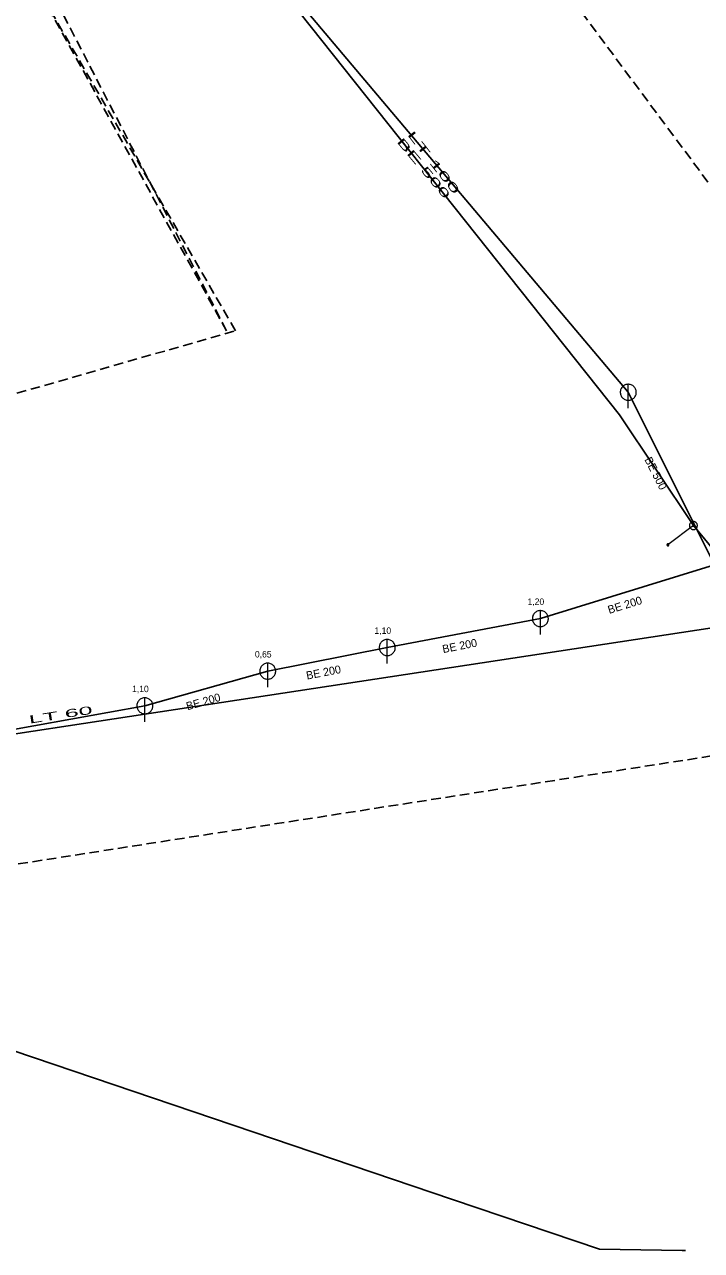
# Model space of a CAD drawing. Extents: x -689820 to -689363, y -975369 to -975062.
# Drawn here: x -689628.7 to -689544.2, y -975368.9 to -975215.7 of the extents above; entities that cross this region are included whole.
import ezdxf

# ---------------------------------------------------------------- set-up
doc = ezdxf.new("R2010")
doc.units = 0
doc.header["$LTSCALE"] = 0.4
doc.linetypes.add('MEDIUM_DASHED', pattern=[4.5, 3, -1.5])
doc.layers.add('1', color=7, linetype='Continuous')
for name, color, linetype, lineweight in [('14', 7, 'Continuous', 25), ('17', 7, 'Continuous', 25), ('22', 7, 'Continuous', 13), ('47', 7, 'Continuous', 13), ('63', 7, 'MEDIUM_DASHED', 25), ('9', 7, 'Continuous', 13)]:
    doc.layers.add(name, color=color, linetype=linetype, lineweight=lineweight)

msp = doc.modelspace()

# ---------------------------------------------------------------- linework, layer by layer
at = {"layer": '14'}
for p, q in [((-689553.342, -975261.657), (-689604.392, -975201.087)), ((-689598.372, -975296.513), (-689583.441, -975293.556)), ((-689613.713, -975300.842), (-689598.372, -975296.513)), ((-689648.44, -975307.089), (-689613.713, -975300.842))]:
    msp.add_line(p, q, dxfattribs=at)
at = {"layer": '14', "lineweight": 13}
msp.add_line((-689545.213, -975278.312), (-689548.389, -975280.719), dxfattribs=at)
at = {"layer": '14'}
msp.add_lwpolyline([(-689583.441, -975293.556), (-689564.324, -975289.938), (-689542.572, -975283.204), (-689553.342, -975261.657)], dxfattribs=at)
at = {"layer": '17'}
msp.add_line((-689536.239, -975289.23), (-689545.213, -975278.312), dxfattribs=at)
for points in [[(-689545.213, -975278.312), (-689554.449, -975264.469), (-689605.354, -975200.364), (-689609.803, -975191.467), (-689614.585, -975177.62)], [(-689536.351, -975289.602), (-689537.203, -975289.743), (-689537.12, -975290.232), (-689713.89, -975317.113)], [(-689546.18, -975368.915), (-689546.615, -975368.909), (-689556.942, -975368.745), (-689575.305, -975362.528), (-689637.592, -975341.438), (-689647.677, -975338.907), (-689651.947, -975337.591), (-689675.142, -975330.715), (-689713.978, -975319.23), (-689713.89, -975317.113)]]:
    msp.add_lwpolyline(points, dxfattribs=at)
at = {"layer": '22'}
for p, q in [((-689553.342, -975263.657), (-689553.341, -975260.657)), ((-689564.324, -975291.938), (-689564.323, -975288.938)), ((-689583.441, -975295.556), (-689583.44, -975292.556)), ((-689598.372, -975298.513), (-689598.371, -975295.513)), ((-689613.713, -975302.842), (-689613.712, -975299.842))]:
    msp.add_line(p, q, dxfattribs=at)
for points in [[(-689552.342, -975261.657), (-689552.347, -975261.548), (-689552.365, -975261.44), (-689552.395, -975261.334), (-689552.435, -975261.233), (-689552.487, -975261.136), (-689552.549, -975261.046), (-689552.621, -975260.963), (-689552.701, -975260.889), (-689552.789, -975260.823), (-689552.883, -975260.768), (-689552.983, -975260.723), (-689553.088, -975260.69), (-689553.195, -975260.668), (-689553.304, -975260.658), (-689553.414, -975260.66), (-689553.522, -975260.674), (-689553.629, -975260.699), (-689553.732, -975260.736), (-689553.83, -975260.785), (-689553.922, -975260.843), (-689554.008, -975260.912), (-689554.085, -975260.989), (-689554.154, -975261.075), (-689554.213, -975261.167), (-689554.261, -975261.265), (-689554.298, -975261.368), (-689554.324, -975261.475), (-689554.338, -975261.583), (-689554.341, -975261.693), (-689554.331, -975261.802), (-689554.31, -975261.909), (-689554.276, -975262.013), (-689554.232, -975262.113), (-689554.177, -975262.208), (-689554.111, -975262.296), (-689554.037, -975262.376), (-689553.954, -975262.448), (-689553.864, -975262.51), (-689553.768, -975262.562), (-689553.666, -975262.603), (-689553.561, -975262.633), (-689553.453, -975262.651), (-689553.343, -975262.657), (-689553.234, -975262.651), (-689553.126, -975262.633), (-689553.021, -975262.604), (-689552.919, -975262.563), (-689552.822, -975262.511), (-689552.732, -975262.449), (-689552.649, -975262.378), (-689552.574, -975262.298), (-689552.509, -975262.21), (-689552.453, -975262.116), (-689552.409, -975262.016), (-689552.375, -975261.912), (-689552.353, -975261.804), (-689552.343, -975261.695)], [(-689563.324, -975289.938), (-689563.329, -975289.829), (-689563.347, -975289.721), (-689563.377, -975289.615), (-689563.417, -975289.514), (-689563.469, -975289.417), (-689563.531, -975289.327), (-689563.603, -975289.244), (-689563.683, -975289.17), (-689563.771, -975289.104), (-689563.865, -975289.049), (-689563.965, -975289.004), (-689564.07, -975288.971), (-689564.177, -975288.949), (-689564.286, -975288.939), (-689564.396, -975288.941), (-689564.504, -975288.955), (-689564.611, -975288.98), (-689564.714, -975289.017), (-689564.812, -975289.066), (-689564.904, -975289.124), (-689564.99, -975289.193), (-689565.067, -975289.27), (-689565.136, -975289.356), (-689565.195, -975289.448), (-689565.243, -975289.546), (-689565.28, -975289.649), (-689565.306, -975289.756), (-689565.32, -975289.864), (-689565.323, -975289.974), (-689565.313, -975290.083), (-689565.292, -975290.19), (-689565.258, -975290.294), (-689565.214, -975290.394), (-689565.159, -975290.489), (-689565.093, -975290.577), (-689565.019, -975290.657), (-689564.936, -975290.729), (-689564.846, -975290.791), (-689564.75, -975290.843), (-689564.648, -975290.884), (-689564.543, -975290.914), (-689564.435, -975290.932), (-689564.325, -975290.938), (-689564.216, -975290.932), (-689564.108, -975290.914), (-689564.003, -975290.885), (-689563.901, -975290.844), (-689563.804, -975290.792), (-689563.714, -975290.73), (-689563.631, -975290.659), (-689563.556, -975290.579), (-689563.491, -975290.491), (-689563.435, -975290.397), (-689563.391, -975290.297), (-689563.357, -975290.193), (-689563.335, -975290.085), (-689563.325, -975289.976)], [(-689582.441, -975293.556), (-689582.446, -975293.447), (-689582.464, -975293.339), (-689582.494, -975293.233), (-689582.534, -975293.132), (-689582.586, -975293.035), (-689582.648, -975292.945), (-689582.72, -975292.862), (-689582.8, -975292.788), (-689582.888, -975292.722), (-689582.982, -975292.667), (-689583.082, -975292.622), (-689583.187, -975292.589), (-689583.294, -975292.567), (-689583.403, -975292.557), (-689583.513, -975292.559), (-689583.621, -975292.573), (-689583.728, -975292.598), (-689583.831, -975292.635), (-689583.929, -975292.684), (-689584.021, -975292.742), (-689584.107, -975292.811), (-689584.184, -975292.888), (-689584.253, -975292.974), (-689584.312, -975293.066), (-689584.36, -975293.164), (-689584.397, -975293.267), (-689584.423, -975293.374), (-689584.437, -975293.482), (-689584.44, -975293.592), (-689584.43, -975293.701), (-689584.409, -975293.808), (-689584.375, -975293.912), (-689584.331, -975294.012), (-689584.276, -975294.107), (-689584.21, -975294.195), (-689584.136, -975294.275), (-689584.053, -975294.347), (-689583.963, -975294.409), (-689583.867, -975294.461), (-689583.765, -975294.502), (-689583.66, -975294.532), (-689583.552, -975294.55), (-689583.442, -975294.556), (-689583.333, -975294.55), (-689583.225, -975294.532), (-689583.12, -975294.503), (-689583.018, -975294.462), (-689582.921, -975294.41), (-689582.831, -975294.348), (-689582.748, -975294.277), (-689582.673, -975294.197), (-689582.608, -975294.109), (-689582.552, -975294.015), (-689582.508, -975293.915), (-689582.474, -975293.811), (-689582.452, -975293.703), (-689582.442, -975293.594)], [(-689597.372, -975296.513), (-689597.377, -975296.404), (-689597.395, -975296.296), (-689597.425, -975296.19), (-689597.465, -975296.089), (-689597.517, -975295.992), (-689597.579, -975295.902), (-689597.651, -975295.819), (-689597.731, -975295.745), (-689597.819, -975295.679), (-689597.913, -975295.624), (-689598.013, -975295.579), (-689598.118, -975295.546), (-689598.225, -975295.524), (-689598.334, -975295.514), (-689598.444, -975295.516), (-689598.552, -975295.53), (-689598.659, -975295.555), (-689598.762, -975295.592), (-689598.86, -975295.641), (-689598.952, -975295.699), (-689599.038, -975295.768), (-689599.115, -975295.845), (-689599.184, -975295.931), (-689599.243, -975296.023), (-689599.291, -975296.121), (-689599.328, -975296.224), (-689599.354, -975296.331), (-689599.368, -975296.439), (-689599.371, -975296.549), (-689599.361, -975296.658), (-689599.34, -975296.765), (-689599.306, -975296.869), (-689599.262, -975296.969), (-689599.207, -975297.064), (-689599.141, -975297.152), (-689599.067, -975297.232), (-689598.984, -975297.304), (-689598.894, -975297.366), (-689598.798, -975297.418), (-689598.696, -975297.459), (-689598.591, -975297.489), (-689598.483, -975297.507), (-689598.373, -975297.513), (-689598.264, -975297.507), (-689598.156, -975297.489), (-689598.051, -975297.46), (-689597.949, -975297.419), (-689597.852, -975297.367), (-689597.762, -975297.305), (-689597.679, -975297.234), (-689597.604, -975297.154), (-689597.539, -975297.066), (-689597.483, -975296.972), (-689597.439, -975296.872), (-689597.405, -975296.768), (-689597.383, -975296.66), (-689597.373, -975296.551)], [(-689612.713, -975300.842), (-689612.718, -975300.733), (-689612.736, -975300.625), (-689612.766, -975300.519), (-689612.806, -975300.418), (-689612.858, -975300.321), (-689612.92, -975300.231), (-689612.992, -975300.148), (-689613.072, -975300.074), (-689613.16, -975300.008), (-689613.254, -975299.953), (-689613.354, -975299.908), (-689613.459, -975299.875), (-689613.566, -975299.853), (-689613.675, -975299.843), (-689613.785, -975299.845), (-689613.893, -975299.859), (-689614, -975299.884), (-689614.103, -975299.921), (-689614.201, -975299.97), (-689614.293, -975300.028), (-689614.379, -975300.097), (-689614.456, -975300.174), (-689614.525, -975300.26), (-689614.584, -975300.352), (-689614.632, -975300.45), (-689614.669, -975300.553), (-689614.695, -975300.66), (-689614.709, -975300.768), (-689614.712, -975300.878), (-689614.702, -975300.987), (-689614.681, -975301.094), (-689614.647, -975301.198), (-689614.603, -975301.298), (-689614.548, -975301.393), (-689614.482, -975301.481), (-689614.408, -975301.561), (-689614.325, -975301.633), (-689614.235, -975301.695), (-689614.139, -975301.747), (-689614.037, -975301.788), (-689613.932, -975301.818), (-689613.824, -975301.836), (-689613.714, -975301.842), (-689613.605, -975301.836), (-689613.497, -975301.818), (-689613.392, -975301.789), (-689613.29, -975301.748), (-689613.193, -975301.696), (-689613.103, -975301.634), (-689613.02, -975301.563), (-689612.945, -975301.483), (-689612.88, -975301.395), (-689612.824, -975301.301), (-689612.78, -975301.201), (-689612.746, -975301.097), (-689612.724, -975300.989), (-689612.714, -975300.88)]]:
    msp.add_lwpolyline(points, close=True, dxfattribs=at)
at = {"layer": '47'}
for points in [[(-689544.955, -975278.74), (-689544.912, -975278.711), (-689544.871, -975278.677), (-689544.836, -975278.639), (-689544.803, -975278.598), (-689544.775, -975278.554), (-689544.752, -975278.506), (-689544.735, -975278.457), (-689544.722, -975278.406), (-689544.715, -975278.355), (-689544.713, -975278.302), (-689544.716, -975278.25), (-689544.726, -975278.199), (-689544.74, -975278.148), (-689544.76, -975278.1), (-689544.784, -975278.054), (-689544.813, -975278.011), (-689544.847, -975277.97), (-689544.885, -975277.934), (-689544.926, -975277.902), (-689544.97, -975277.874), (-689545.018, -975277.851), (-689545.067, -975277.833), (-689545.118, -975277.821), (-689545.169, -975277.813), (-689545.222, -975277.812), (-689545.274, -975277.815), (-689545.326, -975277.824), (-689545.376, -975277.839), (-689545.424, -975277.859), (-689545.47, -975277.883), (-689545.513, -975277.912), (-689545.554, -975277.946), (-689545.591, -975277.984), (-689545.622, -975278.025), (-689545.65, -975278.069), (-689545.673, -975278.116), (-689545.691, -975278.166), (-689545.704, -975278.216), (-689545.711, -975278.268), (-689545.712, -975278.321), (-689545.709, -975278.373), (-689545.7, -975278.424), (-689545.685, -975278.475), (-689545.665, -975278.523), (-689545.641, -975278.569), (-689545.612, -975278.612), (-689545.578, -975278.653), (-689545.541, -975278.689), (-689545.499, -975278.721), (-689545.455, -975278.749), (-689545.408, -975278.772), (-689545.359, -975278.789), (-689545.308, -975278.802), (-689545.256, -975278.809), (-689545.203, -975278.811), (-689545.151, -975278.808), (-689545.1, -975278.798), (-689545.049, -975278.784), (-689545.001, -975278.764)], [(-689545.17, -975278.382), (-689545.163, -975278.377), (-689545.157, -975278.371), (-689545.151, -975278.365), (-689545.146, -975278.359), (-689545.141, -975278.351), (-689545.137, -975278.343), (-689545.134, -975278.335), (-689545.132, -975278.327), (-689545.131, -975278.319), (-689545.131, -975278.31), (-689545.131, -975278.301), (-689545.133, -975278.293), (-689545.135, -975278.285), (-689545.138, -975278.277), (-689545.142, -975278.269), (-689545.147, -975278.262), (-689545.153, -975278.256), (-689545.159, -975278.25), (-689545.165, -975278.245), (-689545.173, -975278.24), (-689545.181, -975278.236), (-689545.189, -975278.233), (-689545.197, -975278.231), (-689545.206, -975278.229), (-689545.214, -975278.23), (-689545.223, -975278.23), (-689545.231, -975278.232), (-689545.239, -975278.234), (-689545.247, -975278.237), (-689545.255, -975278.241), (-689545.262, -975278.246), (-689545.268, -975278.252), (-689545.274, -975278.258), (-689545.279, -975278.264), (-689545.284, -975278.272), (-689545.288, -975278.279), (-689545.291, -975278.288), (-689545.293, -975278.296), (-689545.295, -975278.305), (-689545.294, -975278.313), (-689545.294, -975278.322), (-689545.292, -975278.33), (-689545.29, -975278.338), (-689545.287, -975278.346), (-689545.283, -975278.354), (-689545.278, -975278.361), (-689545.272, -975278.367), (-689545.266, -975278.373), (-689545.26, -975278.378), (-689545.252, -975278.383), (-689545.245, -975278.387), (-689545.236, -975278.39), (-689545.228, -975278.392), (-689545.22, -975278.393), (-689545.211, -975278.393), (-689545.202, -975278.393), (-689545.194, -975278.391), (-689545.186, -975278.389), (-689545.178, -975278.386)]]:
    msp.add_lwpolyline(points, close=True, dxfattribs=at)
at = {"layer": '63'}
msp.add_lwpolyline([(-689662.123, -975114.404), (-689588.993, -975102.123), (-689588.993, -975102.123), (-689580.62, -975185.301), (-689580.62, -975185.301), (-689519.213, -975267.921), (-689519.213, -975267.921), (-689394.167, -975240.009), (-689394.167, -975240.009), (-689384.677, -975282.435), (-689384.677, -975282.435), (-689764.282, -975341.609), (-689764.282, -975341.609), (-689752.559, -975296.95), (-689752.559, -975296.95), (-689602.391, -975253.965), (-689627.512, -975210.422), (-689603.508, -975253.965), (-689648.167, -975167.437), (-689648.167, -975167.437)], close=True, dxfattribs=at)
at = {"layer": '9'}
for points in [[(-689548.515, -975280.719), (-689548.515, -975280.732), (-689548.512, -975280.745), (-689548.51, -975280.758), (-689548.505, -975280.77), (-689548.499, -975280.782), (-689548.492, -975280.793), (-689548.483, -975280.803), (-689548.473, -975280.813), (-689548.463, -975280.821), (-689548.453, -975280.828), (-689548.441, -975280.834), (-689548.429, -975280.839), (-689548.416, -975280.842), (-689548.402, -975280.844), (-689548.39, -975280.846), (-689548.377, -975280.845), (-689548.364, -975280.843), (-689548.351, -975280.84), (-689548.338, -975280.835), (-689548.326, -975280.829), (-689548.316, -975280.822), (-689548.306, -975280.814), (-689548.296, -975280.804), (-689548.288, -975280.794), (-689548.281, -975280.783), (-689548.275, -975280.771), (-689548.27, -975280.759), (-689548.267, -975280.746), (-689548.265, -975280.733), (-689548.262, -975280.72), (-689548.264, -975280.707), (-689548.266, -975280.694), (-689548.269, -975280.681), (-689548.274, -975280.669), (-689548.279, -975280.657), (-689548.287, -975280.646), (-689548.294, -975280.636), (-689548.304, -975280.626), (-689548.315, -975280.618), (-689548.326, -975280.611), (-689548.338, -975280.605), (-689548.35, -975280.6), (-689548.363, -975280.597), (-689548.375, -975280.595), (-689548.389, -975280.594), (-689548.402, -975280.594), (-689548.414, -975280.596), (-689548.428, -975280.599), (-689548.44, -975280.604), (-689548.451, -975280.61), (-689548.463, -975280.617), (-689548.473, -975280.625), (-689548.483, -975280.635), (-689548.49, -975280.645), (-689548.498, -975280.656), (-689548.504, -975280.668), (-689548.509, -975280.68), (-689548.512, -975280.693), (-689548.514, -975280.706)], [(-689548.495, -975280.719), (-689548.495, -975280.73), (-689548.494, -975280.741), (-689548.49, -975280.752), (-689548.487, -975280.762), (-689548.482, -975280.772), (-689548.476, -975280.781), (-689548.468, -975280.79), (-689548.461, -975280.798), (-689548.451, -975280.805), (-689548.443, -975280.811), (-689548.433, -975280.816), (-689548.423, -975280.82), (-689548.412, -975280.823), (-689548.401, -975280.826), (-689548.39, -975280.826), (-689548.379, -975280.826), (-689548.368, -975280.824), (-689548.357, -975280.821), (-689548.347, -975280.817), (-689548.337, -975280.812), (-689548.328, -975280.806), (-689548.319, -975280.799), (-689548.311, -975280.791), (-689548.304, -975280.782), (-689548.298, -975280.773), (-689548.293, -975280.763), (-689548.289, -975280.753), (-689548.286, -975280.742), (-689548.284, -975280.731), (-689548.282, -975280.72), (-689548.282, -975280.709), (-689548.284, -975280.698), (-689548.288, -975280.687), (-689548.292, -975280.677), (-689548.297, -975280.667), (-689548.303, -975280.658), (-689548.309, -975280.649), (-689548.318, -975280.641), (-689548.326, -975280.634), (-689548.336, -975280.628), (-689548.346, -975280.623), (-689548.355, -975280.619), (-689548.367, -975280.616), (-689548.377, -975280.614), (-689548.389, -975280.614), (-689548.4, -975280.613), (-689548.411, -975280.615), (-689548.422, -975280.618), (-689548.431, -975280.622), (-689548.441, -975280.627), (-689548.451, -975280.633), (-689548.46, -975280.64), (-689548.468, -975280.648), (-689548.475, -975280.657), (-689548.48, -975280.666), (-689548.485, -975280.676), (-689548.49, -975280.686), (-689548.493, -975280.697), (-689548.495, -975280.708)], [(-689548.476, -975280.719), (-689548.476, -975280.728), (-689548.475, -975280.737), (-689548.472, -975280.746), (-689548.468, -975280.754), (-689548.465, -975280.762), (-689548.46, -975280.77), (-689548.453, -975280.777), (-689548.448, -975280.783), (-689548.441, -975280.789), (-689548.433, -975280.794), (-689548.424, -975280.798), (-689548.417, -975280.801), (-689548.407, -975280.804), (-689548.399, -975280.805), (-689548.39, -975280.807), (-689548.38, -975280.806), (-689548.372, -975280.805), (-689548.363, -975280.802), (-689548.355, -975280.799), (-689548.347, -975280.795), (-689548.338, -975280.79), (-689548.331, -975280.784), (-689548.326, -975280.778), (-689548.32, -975280.771), (-689548.315, -975280.763), (-689548.311, -975280.755), (-689548.308, -975280.747), (-689548.304, -975280.738), (-689548.304, -975280.729), (-689548.301, -975280.72), (-689548.303, -975280.711), (-689548.304, -975280.702), (-689548.306, -975280.693), (-689548.309, -975280.685), (-689548.314, -975280.677), (-689548.319, -975280.669), (-689548.325, -975280.662), (-689548.331, -975280.656), (-689548.338, -975280.65), (-689548.346, -975280.645), (-689548.353, -975280.641), (-689548.362, -975280.638), (-689548.37, -975280.635), (-689548.38, -975280.634), (-689548.389, -975280.633), (-689548.397, -975280.633), (-689548.407, -975280.634), (-689548.416, -975280.637), (-689548.424, -975280.64), (-689548.431, -975280.644), (-689548.44, -975280.649), (-689548.446, -975280.655), (-689548.453, -975280.661), (-689548.458, -975280.668), (-689548.463, -975280.676), (-689548.468, -975280.684), (-689548.471, -975280.692), (-689548.473, -975280.701), (-689548.475, -975280.71)], [(-689548.456, -975280.719), (-689548.456, -975280.726), (-689548.455, -975280.733), (-689548.453, -975280.74), (-689548.451, -975280.746), (-689548.448, -975280.752), (-689548.444, -975280.758), (-689548.44, -975280.764), (-689548.434, -975280.769), (-689548.429, -975280.773), (-689548.423, -975280.777), (-689548.417, -975280.78), (-689548.411, -975280.783), (-689548.404, -975280.784), (-689548.397, -975280.787), (-689548.39, -975280.787), (-689548.382, -975280.787), (-689548.375, -975280.785), (-689548.369, -975280.784), (-689548.363, -975280.781), (-689548.355, -975280.778), (-689548.351, -975280.774), (-689548.345, -975280.77), (-689548.34, -975280.765), (-689548.336, -975280.759), (-689548.331, -975280.753), (-689548.328, -975280.747), (-689548.326, -975280.741), (-689548.324, -975280.734), (-689548.323, -975280.727), (-689548.321, -975280.72), (-689548.321, -975280.713), (-689548.323, -975280.706), (-689548.325, -975280.699), (-689548.328, -975280.693), (-689548.331, -975280.686), (-689548.335, -975280.681), (-689548.338, -975280.675), (-689548.343, -975280.67), (-689548.35, -975280.666), (-689548.355, -975280.662), (-689548.362, -975280.659), (-689548.368, -975280.656), (-689548.375, -975280.654), (-689548.382, -975280.653), (-689548.389, -975280.653), (-689548.396, -975280.653), (-689548.402, -975280.653), (-689548.409, -975280.655), (-689548.416, -975280.658), (-689548.422, -975280.661), (-689548.428, -975280.665), (-689548.434, -975280.669), (-689548.439, -975280.674), (-689548.443, -975280.68), (-689548.446, -975280.685), (-689548.45, -975280.692), (-689548.453, -975280.698), (-689548.453, -975280.705), (-689548.456, -975280.712)], [(-689548.436, -975280.719), (-689548.436, -975280.724), (-689548.436, -975280.729), (-689548.434, -975280.734), (-689548.433, -975280.738), (-689548.431, -975280.743), (-689548.428, -975280.747), (-689548.424, -975280.75), (-689548.421, -975280.754), (-689548.418, -975280.757), (-689548.414, -975280.76), (-689548.409, -975280.762), (-689548.404, -975280.764), (-689548.4, -975280.765), (-689548.395, -975280.767), (-689548.39, -975280.767), (-689548.385, -975280.767), (-689548.38, -975280.766), (-689548.375, -975280.765), (-689548.37, -975280.763), (-689548.365, -975280.761), (-689548.362, -975280.758), (-689548.358, -975280.755), (-689548.355, -975280.751), (-689548.352, -975280.748), (-689548.348, -975280.744), (-689548.347, -975280.739), (-689548.345, -975280.735), (-689548.343, -975280.73), (-689548.343, -975280.725), (-689548.342, -975280.72), (-689548.342, -975280.715), (-689548.343, -975280.71), (-689548.343, -975280.705), (-689548.346, -975280.701), (-689548.348, -975280.696), (-689548.351, -975280.692), (-689548.353, -975280.688), (-689548.357, -975280.685), (-689548.36, -975280.682), (-689548.365, -975280.679), (-689548.37, -975280.677), (-689548.374, -975280.675), (-689548.379, -975280.674), (-689548.384, -975280.673), (-689548.389, -975280.673), (-689548.394, -975280.673), (-689548.399, -975280.674), (-689548.404, -975280.674), (-689548.407, -975280.676), (-689548.413, -975280.678), (-689548.417, -975280.681), (-689548.419, -975280.684), (-689548.424, -975280.687), (-689548.426, -975280.691), (-689548.429, -975280.695), (-689548.431, -975280.7), (-689548.434, -975280.704), (-689548.434, -975280.709), (-689548.436, -975280.714)], [(-689548.416, -975280.719), (-689548.416, -975280.722), (-689548.417, -975280.725), (-689548.416, -975280.727), (-689548.414, -975280.73), (-689548.414, -975280.733), (-689548.412, -975280.735), (-689548.409, -975280.737), (-689548.407, -975280.739), (-689548.406, -975280.741), (-689548.404, -975280.743), (-689548.401, -975280.745), (-689548.397, -975280.746), (-689548.396, -975280.746), (-689548.392, -975280.747), (-689548.39, -975280.747), (-689548.387, -975280.747), (-689548.384, -975280.747), (-689548.38, -975280.746), (-689548.379, -975280.745), (-689548.375, -975280.744), (-689548.374, -975280.742), (-689548.37, -975280.74), (-689548.369, -975280.738), (-689548.368, -975280.736), (-689548.365, -975280.734), (-689548.365, -975280.731), (-689548.363, -975280.728), (-689548.363, -975280.726), (-689548.362, -975280.723), (-689548.36, -975280.72), (-689548.362, -975280.717), (-689548.362, -975280.714), (-689548.363, -975280.711), (-689548.364, -975280.709), (-689548.365, -975280.706), (-689548.367, -975280.704), (-689548.368, -975280.701), (-689548.37, -975280.699), (-689548.373, -975280.698), (-689548.375, -975280.696), (-689548.377, -975280.695), (-689548.38, -975280.694), (-689548.382, -975280.693), (-689548.386, -975280.693), (-689548.389, -975280.692), (-689548.392, -975280.693), (-689548.395, -975280.692), (-689548.397, -975280.694), (-689548.4, -975280.694), (-689548.402, -975280.695), (-689548.404, -975280.697), (-689548.407, -975280.698), (-689548.409, -975280.7), (-689548.411, -975280.703), (-689548.413, -975280.705), (-689548.414, -975280.708), (-689548.414, -975280.71), (-689548.416, -975280.713), (-689548.416, -975280.716)], [(-689548.397, -975280.719), (-689548.397, -975280.721), (-689548.397, -975280.721), (-689548.396, -975280.721), (-689548.396, -975280.723), (-689548.397, -975280.724), (-689548.395, -975280.724), (-689548.395, -975280.724), (-689548.395, -975280.726), (-689548.395, -975280.726), (-689548.394, -975280.727), (-689548.392, -975280.727), (-689548.392, -975280.727), (-689548.392, -975280.728), (-689548.39, -975280.728), (-689548.39, -975280.728), (-689548.389, -975280.728), (-689548.387, -975280.728), (-689548.387, -975280.727), (-689548.387, -975280.727), (-689548.385, -975280.727), (-689548.385, -975280.726), (-689548.385, -975280.726), (-689548.384, -975280.725), (-689548.384, -975280.725), (-689548.382, -975280.724), (-689548.382, -975280.723), (-689548.38, -975280.722), (-689548.38, -975280.722), (-689548.38, -975280.721), (-689548.38, -975280.72), (-689548.38, -975280.719), (-689548.38, -975280.718), (-689548.38, -975280.718), (-689548.382, -975280.717), (-689548.382, -975280.716), (-689548.382, -975280.715), (-689548.382, -975280.715), (-689548.384, -975280.714), (-689548.384, -975280.714), (-689548.385, -975280.713), (-689548.386, -975280.713), (-689548.387, -975280.712), (-689548.387, -975280.712), (-689548.387, -975280.712), (-689548.389, -975280.712), (-689548.39, -975280.712), (-689548.391, -975280.712), (-689548.391, -975280.712), (-689548.392, -975280.713), (-689548.392, -975280.712), (-689548.394, -975280.714), (-689548.394, -975280.714), (-689548.395, -975280.714), (-689548.395, -975280.714), (-689548.396, -975280.716), (-689548.396, -975280.717), (-689548.396, -975280.718), (-689548.397, -975280.718), (-689548.397, -975280.719)]]:
    msp.add_lwpolyline(points, close=True, dxfattribs=at)

# ---------------------------------------------------------------- texts
at = {"layer": '1'}
for s, rotation, width, p in [('LT 100', 308, 2.3, (-689580.995, -975229.454)), ('BE 500', 310, 2.15, (-689582.317, -975230.357)), ('LT 60 ', 9, 2.35, (-689628.124, -975303.074))]:
    msp.add_text(s, height=1, rotation=rotation, dxfattribs=dict(at, width=width)).set_placement(p)
for s, rotation, p in [('BE 500', 297, (-689551.36, -975270.06)), ('BE 200', 17, (-689555.727, -975289.354)), ('BE 200', 11, (-689576.46, -975294.255)), ('BE 200', 11, (-689593.463, -975297.564)), ('BE 200', 16, (-689608.39, -975301.403))]:
    msp.add_text(s, height=1, rotation=rotation, dxfattribs=at).set_placement(p)
for s, p in [('1,20', (-689565.924, -975288.227)), ('1,10', (-689585.041, -975291.845)), ('0,65', (-689599.971, -975294.801)), ('1,10', (-689615.312, -975299.131))]:
    msp.add_text(s, height=0.8, dxfattribs=at).set_placement(p)

doc.saveas('drawing.dxf')
